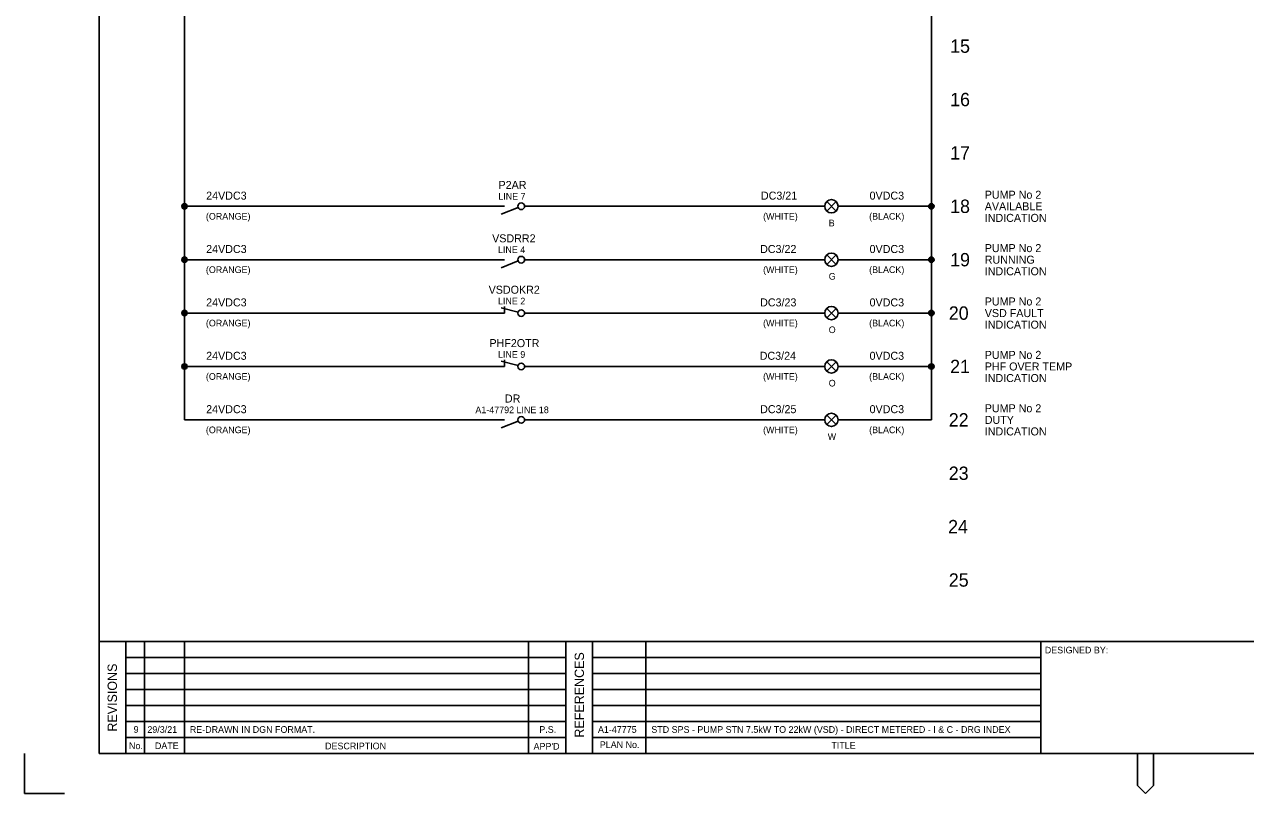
# Model space of a CAD drawing. Extents: x 0 to 841, y 0 to 594.
# Drawn here: x 0 to 457.8, y 0 to 288.1 of the extents above; entities that cross this region are included whole.
import ezdxf

# ---------------------------------------------------------------- set-up
doc = ezdxf.new("R2010")
doc.units = 0
for name, color, linetype in [('A1BORDER', 7, 'Continuous'), ('Level 1', 7, 'Continuous'), ('Level 10', 7, 'Continuous'), ('Level 5', 7, 'Continuous'), ('Level 6', 7, 'Continuous')]:
    doc.layers.add(name, color=color, linetype=linetype)

msp = doc.modelspace()

# ---------------------------------------------------------------- linework, layer by layer
at = {"layer": 'A1BORDER'}
for p, q in [((28, 581), (28, 15)), ((28, 57), (829, 57)), ((38, 15), (38, 57)), ((45, 15), (45, 57)), ((60, 15), (60, 57)), ((189, 15), (189, 57)), ((203, 15), (203, 57)), ((213, 15), (213, 57)), ((233, 15), (233, 57)), ((381, 15), (381, 57)), ((203, 51), (38, 51)), ((213, 51), (381, 51)), ((203, 45), (38, 45)), ((213, 45), (381, 45)), ((203, 39), (38, 39)), ((213, 39), (381, 39)), ((203, 33), (38, 33)), ((213, 33), (381, 33)), ((38, 27), (203, 27)), ((213, 27), (381, 27)), ((203, 21), (38, 21)), ((213, 21), (381, 21)), ((0, 0), (0, 15)), ((829, 15), (28, 15)), ((417.19, 15), (417.19, 3)), ((423.19, 15), (423.19, 3)), ((417.19, 3), (420.19, 0)), ((423.19, 3), (420.19, 0)), ((0, 0), (15, 0))]:
    msp.add_line(p, q, dxfattribs=at)
at = {"layer": 'Level 1'}
for p, q in [((60, 160), (60, 560)), ((340, 160), (340, 560)), ((60, 140), (60, 520)), ((340, 140), (340, 520)), ((60, 220), (177.5, 220)), ((180, 220), (177.5, 220)), ((177.5, 220), (177.5, 220)), ((187.5, 220), (187.5, 220)), ((305, 220), (340, 220)), ((60, 200), (177.5, 200)), ((180, 200), (177.5, 200)), ((177.5, 200), (177.5, 200)), ((187.5, 200), (187.5, 200)), ((305, 200), (340, 200)), ((60, 180), (177.5, 180)), ((180, 180), (177.5, 180)), ((305, 180), (340, 180)), ((60, 160), (177.5, 160)), ((180, 160), (177.5, 160)), ((305, 160), (340, 160)), ((60, 140), (177.5, 140)), ((180, 140), (177.5, 140)), ((177.5, 140), (177.5, 140)), ((187.5, 140), (187.5, 140)), ((305, 140), (340, 140))]:
    msp.add_line(p, q, dxfattribs=at)
at = {"layer": 'Level 10'}
for p, q in [((59.1, 220.44), (59.1, 219.56)), ((59.4, 220.8), (59.4, 219.2)), ((59.7, 220.95), (59.7, 219.05)), ((60, 221), (60, 219.01)), ((60.3, 220.95), (60.3, 219.05)), ((60.6, 220.8), (60.6, 219.2)), ((60.9, 220.44), (60.9, 219.56)), ((61, 220), (61, 220)), ((304.27, 221.77), (300.73, 218.23)), ((300.73, 221.77), (304.27, 218.23)), ((339.1, 220.44), (339.1, 219.56)), ((339.4, 220.8), (339.4, 219.2)), ((339.7, 220.95), (339.7, 219.05)), ((340, 221), (340, 219.01)), ((340.3, 220.95), (340.3, 219.05)), ((340.6, 220.8), (340.6, 219.2)), ((340.9, 220.44), (340.9, 219.56)), ((341, 220), (341, 220)), ((185.09, 219.54), (178.75, 217)), ((304.27, 201.77), (300.73, 198.23)), ((300.73, 201.77), (304.27, 198.23)), ((59.1, 200.44), (59.1, 199.56)), ((59.4, 200.8), (59.4, 199.2)), ((59.7, 200.95), (59.7, 199.05)), ((60, 201), (60, 199.01)), ((60.3, 200.95), (60.3, 199.05)), ((60.6, 200.8), (60.6, 199.2)), ((60.9, 200.44), (60.9, 199.56)), ((61, 200), (61, 200)), ((185.09, 199.54), (178.75, 197)), ((339.1, 200.44), (339.1, 199.56)), ((339.4, 200.8), (339.4, 199.2)), ((339.7, 200.95), (339.7, 199.05)), ((340, 201), (340, 199.01)), ((340.3, 200.95), (340.3, 199.05)), ((340.6, 200.8), (340.6, 199.2)), ((340.9, 200.44), (340.9, 199.56)), ((341, 200), (341, 200)), ((59.1, 180.44), (59.1, 179.56)), ((59.4, 180.8), (59.4, 179.2)), ((59.7, 180.95), (59.7, 179.05)), ((60, 181), (60, 179.01)), ((60.3, 180.95), (60.3, 179.05)), ((60.6, 180.8), (60.6, 179.2)), ((60.9, 180.44), (60.9, 179.56)), ((61, 180), (61, 180)), ((185.04, 180.32), (178.75, 182)), ((180, 182.5), (180, 180)), ((304.27, 181.77), (300.73, 178.23)), ((300.73, 181.77), (304.27, 178.23)), ((339.1, 180.44), (339.1, 179.56)), ((339.4, 180.8), (339.4, 179.2)), ((339.7, 180.95), (339.7, 179.05)), ((340, 181), (340, 179.01)), ((340.3, 180.95), (340.3, 179.05)), ((340.6, 180.8), (340.6, 179.2)), ((340.9, 180.44), (340.9, 179.56)), ((341, 180), (341, 180)), ((59.1, 160.44), (59.1, 159.56)), ((59.4, 160.8), (59.4, 159.2)), ((59.7, 160.95), (59.7, 159.05)), ((60, 161), (60, 159.01)), ((60.3, 160.95), (60.3, 159.05)), ((60.6, 160.8), (60.6, 159.2)), ((60.9, 160.44), (60.9, 159.56)), ((185.04, 160.32), (178.75, 162)), ((180, 162.5), (180, 160)), ((304.27, 161.77), (300.73, 158.23)), ((300.73, 161.77), (304.27, 158.23)), ((339.1, 160.44), (339.1, 159.56)), ((339.4, 160.8), (339.4, 159.2)), ((339.7, 160.95), (339.7, 159.05)), ((340, 161), (340, 159.01)), ((340.3, 160.95), (340.3, 159.05)), ((340.6, 160.8), (340.6, 159.2)), ((340.9, 160.44), (340.9, 159.56)), ((61, 160), (61, 160)), ((341, 160), (341, 160)), ((185.09, 139.54), (178.75, 137)), ((304.27, 141.77), (300.73, 138.23)), ((300.73, 141.77), (304.27, 138.23))]:
    msp.add_line(p, q, dxfattribs=at)
for centre, radius in [((60, 220), 1), ((186.25, 220), 1.25), ((302.5, 220), 2.5), ((340, 220), 1), ((302.5, 200), 2.5), ((60, 200), 1), ((186.25, 200), 1.25), ((340, 200), 1), ((60, 180), 1), ((186.25, 180), 1.25), ((302.5, 180), 2.5), ((340, 180), 1), ((60, 160), 1), ((186.25, 160), 1.25), ((302.5, 160), 2.5), ((340, 160), 1), ((302.5, 140), 2.5), ((186.25, 140), 1.25)]:
    msp.add_circle(centre, radius, dxfattribs=at)
at = {"layer": 'Level 6'}
for p, q in [((187.5, 220), (300, 220)), ((187.5, 200), (300, 200)), ((187.5, 180), (300, 180)), ((187.5, 160), (300, 160)), ((187.5, 140), (300, 140))]:
    msp.add_line(p, q, dxfattribs=at)

# ---------------------------------------------------------------- texts
at = {"layer": 'A1BORDER'}
for s, p in [('DESIGNED BY:', (382.5, 52.5)), ('No.', (39.21, 16.65)), ('DATE', (48.92, 16.65)), ('DESCRIPTION', (112.71, 16.57)), ("APP'D", (190.85, 16.44)), ('PLAN No.', (215.69, 17.06)), ('TITLE', (302.5, 16.81))]:
    msp.add_text(s, height=2.5, dxfattribs=at).set_placement(p)
for s, p in [('REFERENCES', (209.76, 20.96)), ('REVISIONS', (34.68, 23.2))]:
    msp.add_text(s, height=3.5, rotation=90, dxfattribs=at).set_placement(p)
at = {"layer": 'Level 1'}
for s, height, p in [('15', 5, (347.01, 277.5)), ('16', 5, (347.01, 257.5)), ('17', 5, (347.01, 237.5)), ('18', 5, (347.01, 217.5)), ('19', 5, (347.01, 197.5)), ('20', 5, (346.51, 177.5)), ('21', 5, (347.01, 157.5)), ('22', 5, (346.51, 137.5)), ('23', 5, (346.51, 117.5)), ('24', 5, (346.26, 97.5)), ('25', 5, (346.51, 77.5)), ('9', 2.5, (40.94, 22.75)), ('29/3/21', 2.5, (46.09, 22.75)), ('RE-DRAWN IN DGN FORMAT.', 2.5, (62, 22.75)), ('P.S.', 2.5, (193.02, 22.75)), ('A1-47775', 2.5, (215, 22.75)), ('STD SPS - PUMP STN 7.5kW TO 22kW (VSD) - DIRECT METERED - I & C - DRG INDEX', 2.5, (235, 22.75))]:
    msp.add_text(s, height=height, dxfattribs=at).set_placement(p)
at = {"layer": 'Level 5'}
for s, height, p in [('P2AR', 3, (177.72, 226.5)), ('24VDC3', 3, (68.13, 222.5)), ('LINE 7', 2.5, (177.64, 222.5)), ('DC3/21', 3, (276.08, 222.5)), ('0VDC3', 3, (316.82, 222.5)), ('PUMP No 2', 3, (360, 222.84)), ('AVAILABLE', 3, (360, 218.5)), ('(ORANGE)', 2.5, (68.03, 215)), ('(WHITE)', 2.5, (276.9, 215)), ('(BLACK)', 2.5, (316.65, 215)), ('INDICATION', 3, (360, 214.16)), ('B', 2.5, (301.5, 212.5)), ('VSDRR2', 3, (175.33, 206.5)), ('24VDC3', 3, (68.13, 202.5)), ('LINE 4', 2.5, (177.52, 202.5)), ('DC3/22', 3, (275.78, 202.5)), ('0VDC3', 3, (316.82, 202.5)), ('PUMP No 2', 3, (360, 202.84)), ('RUNNING', 3, (360, 198.5)), ('(ORANGE)', 2.5, (68.03, 195)), ('(WHITE)', 2.5, (276.9, 195)), ('(BLACK)', 2.5, (316.65, 195)), ('INDICATION', 3, (360, 194.16)), ('G', 2.5, (301.5, 192.5)), ('VSDOKR2', 3, (174.02, 187.25)), ('24VDC3', 3, (68.13, 182.5)), ('LINE 2', 2.5, (177.53, 183.25)), ('DC3/23', 3, (275.78, 182.5)), ('0VDC3', 3, (316.82, 182.5)), ('PUMP No 2', 3, (360, 182.84)), ('VSD FAULT', 3, (360, 178.5)), ('(ORANGE)', 2.5, (68.03, 175)), ('(WHITE)', 2.5, (276.9, 175)), ('O', 2.5, (301.5, 172.5)), ('(BLACK)', 2.5, (316.65, 175)), ('INDICATION', 3, (360, 174.16)), ('PHF2OTR', 3, (174.32, 167.25)), ('24VDC3', 3, (68.13, 162.5)), ('LINE 9', 2.5, (177.53, 163.25)), ('DC3/24', 3, (275.63, 162.5)), ('0VDC3', 3, (316.82, 162.5)), ('PUMP No 2', 3, (360, 162.84)), ('PHF OVER TEMP', 3, (360, 158.5)), ('(ORANGE)', 2.5, (68.03, 155)), ('(WHITE)', 2.5, (276.9, 155)), ('(BLACK)', 2.5, (316.65, 155)), ('INDICATION', 3, (360, 154.16)), ('O', 2.5, (301.5, 152.5)), ('DR', 3, (180.11, 146.5)), ('24VDC3', 3, (68.13, 142.5)), ('A1-47792 LINE 18', 2.5, (169.05, 142.5)), ('DC3/25', 3, (275.78, 142.5)), ('0VDC3', 3, (316.82, 142.5)), ('PUMP No 2', 3, (360, 142.84)), ('(ORANGE)', 2.5, (68.03, 135)), ('(WHITE)', 2.5, (276.9, 135)), ('(BLACK)', 2.5, (316.65, 135)), ('DUTY', 3, (360, 138.5)), ('W', 2.5, (301.13, 132.5)), ('INDICATION', 3, (360, 134.16))]:
    msp.add_text(s, height=height, dxfattribs=at).set_placement(p)

doc.saveas('drawing.dxf')
